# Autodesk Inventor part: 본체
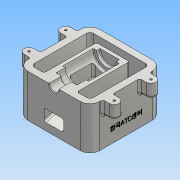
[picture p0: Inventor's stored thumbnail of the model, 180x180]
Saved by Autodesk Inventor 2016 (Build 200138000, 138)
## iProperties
Created: 2018-01
Part Number: 본체
Material: 알루미늄 6061
Document SubType Name: Modeling
Designer: Administrator
Density: 2.7 g/cm^3
Appearance: 알루미늄 - 평지
Mass: 995.217 g
Surface Area: 834.407 cm^2
Volume: 368.599 cm^3
Author: Administrator
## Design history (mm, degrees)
sketch "스케치1"
  geometry: L1 (-55, -55)-(55, -55); L2 (55, -55)-(55, -35.5); L3 (55, 55)-(-55, 55); L4 (-55, 55)-(-55, 35.5); L5 (-55, -55)-(55, 55); L6 (55, -55)-(-55, 55); L7 (-65, -20.5)-(-55, -20.5); L8 (-55, -20.5)-(-55, -35.5); L9 (-55, -35.5)-(-65, -35.5); L10 (-65, -35.5)-(-65, -20.5); L11 (-65, 20.5)-(-55, 20.5); L12 (-55, 20.5)-(-55, 35.5); L13 (-55, 35.5)-(-65, 35.5); L14 (-65, 35.5)-(-65, 20.5); L15 (0, 55)-(0, -55); L16 (55, 35.5)-(65, 35.5); L17 (65, 20.5)-(55, 20.5); L18 (65, -20.5)-(55, -20.5); L19 (55, -35.5)-(65, -35.5); L20 (65, -35.5)-(65, -20.5); L21 (65, 35.5)-(65, 20.5); L22 (-55, 35.5)-(-55, 20.5); L23 (-55, 20.5)-(-55, -20.5); L24 (-55, -20.5)-(-55, -35.5); L25 (-55, -35.5)-(-55, -55); L26 (55, -35.5)-(55, -20.5); L27 (55, -20.5)-(55, 20.5); L28 (55, 20.5)-(55, 35.5); L29 (55, 35.5)-(55, 55); A1 r 7.5 centre (-65, -28) between (-65, -20.5) and (-65, -35.5); A2 r 7.5 centre (-65, 28) between (-65, 35.5) and (-65, 20.5); A3 r 7.5 centre (65, -28) between (65, -35.5) and (65, -20.5); A4 r 7.5 centre (65, 28) between (65, 20.5) and (65, 35.5); 3 further points
  constraints: 58 end point, 30 parallel, 10 symmetric about line, 9 midpoint, 8 point on circle, 7 perpendicular, 4 centre point, 4 point on line, 3 horizontal, 2 other
  dimensions: "d0" = 110 distance of L3.end L3.start; "d1" = 110 distance of L3.start L1.end; "d2" = 27 distance of L3.end point (-55, 28); "d3" = 56 distance of point (-55, -28) point (-55, 28); "d4" = 10 distance of L4.end L13.end; "d5" = 7.5 radius of A2; "d6" = 7.5 radius of A1
extrude "돌출1" new body sketch "스케치1" distance "d7" = 65; taper "d8" = 0 deg
sketch "스케치2"
  geometry: L1 (-55, 55)-(-55, -55) reference; L2 (-65, 35.5)-(-55, 35.5); L3 (-55, 35.5)-(-55, 20.5); L4 (-55, 20.5)-(-65, 20.5); L5 (-65, 20.5)-(-65, 35.5); L6 (-65, -20.5)-(-55, -20.5); L7 (-55, -20.5)-(-55, -35.5); L8 (-55, -35.5)-(-65, -35.5); L9 (-65, -35.5)-(-65, -20.5); L10 (0, 0)-(0, 16.819); L11 (55, -35.5)-(65, -35.5); L12 (65, -35.5)-(65, -20.5); L13 (65, -20.5)-(55, -20.5); L14 (55, 20.5)-(65, 20.5); L15 (65, 20.5)-(65, 35.5); L16 (65, 35.5)-(55, 35.5); A1 r 7.5 centre (-65, 28) between (-65, 35.5) and (-65, 20.5); A2 r 7.5 centre (-65, -28) between (-65, -20.5) and (-65, -35.5); A3 r 7.5 centre (65, -28) between (65, -35.5) and (65, -20.5); A4 r 7.5 centre (65, 28) between (65, 20.5) and (65, 35.5); 1 further point
  constraints: 30 end point, 10 symmetric about line, 8 point on circle, 4 centre point, 4 parallel, 4 point on line, 3 midpoint, 2 horizontal, 2 perpendicular, 1 vertical, 2 other
  dimensions: "d9" = 10 distance of L2.start L2.end; "d10" = 7.5 radius of A1; "d11" = 7.5 radius of A2; "d12" = 27 vertical distance of A1.centre L1.start; "d13" = 56 distance of A2.centre A1.centre
extrude "돌출2" join sketch "스케치2" distance "d14" = 20; taper "d15" = 0 deg
feature "쉘1" dims "d16" = 10
sketch "스케치3"
  geometry: L1 (-45, 0)-(-45, 65) reference; L2 (-45, 8.564)-(35, 30); L3 (45, 0)-(-45, 0) reference; L4 (35, 30)-(35, 65); L5 (20.5, 65)-(-20.5, 65) reference; L6 (-55, 0)-(-55, 65) reference; L7 (-45, 8.564)-(-55, 10.787); L8 (35, 65)-(-45, 65); L9 (-35.5, 65)-(-55, 65) reference; L10 (45, 0)-(45, 65) reference; L11 (55, 0)-(55, 65) reference; 1 further point
  constraints: 8 end point, 3 point on line, 1 collinear, 1 vertical
  dimensions: "d17" = 30 distance from line of L3 L2.end; "d18" = 105 deg angle of L1 L2; "d38" = 20 distance between parallel lines of L11 L4
extrude "돌출3" join sketch "스케치3" stored distance "d22" = 50; taper "d23" = 0 deg
sketch "스케치7"
  geometry: L1 (-55, 0)-(-55, 65) reference; L2 (-55, 11.061)-(20, 31.157); L3 (35, 65)-(35, 30) reference; L4 (35, 30)-(-45, 8.564) reference; L5 (-55, 29.061)-(-17, 39.243); L6 (-17, 39.243)-(-17, 57.924); L7 (20, 31.157)-(20, 57.924); L8 (-17, 57.924)-(-17, 63.66); L9 (20, 57.924)-(20, 63.66); L10 (-17, 63.66)-(20, 63.66); L11 (20.5, 65)-(-20.5, 65) reference; L12 (-55, 29.061)-(-55, 11.061); 1 further point
  constraints: 16 end point, 4 vertical, 2 point on line, 1 collinear, 1 parallel
  dimensions: "d33" = 15 distance from line of L3 L2.end; "d34" = 5 distance between parallel lines of L4 L2; "d35" = 18 distance of L2.start L5.start; "d36" = 75 deg angle of L5 L1; "d37" = 37 distance between parallel lines of L6 L7
extrude "돌출4" cut sketch "스케치7" stored distance "d39" = 30; taper "d40" = 0 deg
sketch "스케치9"
  geometry: L1 (-25, 35)-(25, 35) reference; L2 (-55, -55)-(55, -55) reference; L3 (0, 35)-(0, -55); L4 (-55, -55)-(55, -55) reference; L5 (-7.5, -55)-(-7.5, -36); L6 (-16, -22)-(-16, -36); L7 (-20, 25)-(-20, -22); L8 (-15, 30)-(-15, 25); L9 (-15, 25)-(-20, 25); L10 (-20, -22)-(-16, -22); L11 (-16, -36)-(-7.5, -36); L12 (-15, 30)-(0, 30); L13 (-7.5, -55)-(0, -55); 1 further point
  constraints: 20 end point, 4 perpendicular, 3 vertical, 2 midpoint, 2 point on line, 1 collinear, 1 horizontal
  dimensions: "d41" = 15 diameter of L5 L3; "d42" = 32 diameter of L6 L3; "d43" = 40 diameter of L7 L3; "d44" = 30 diameter of L8 L3; "d45" = 5 distance of L8.start L8.end; "d46" = 47 distance of L7.start L7.end; "d47" = 14 distance of L6.start L6.end; "d48" = 19 distance of L5.start L5.end
revolve "회전1" sketch "스케치9" stored, may be unused: angle "d49" = 90 deg
hole "구멍1" diameter "d52" = 3.242; stored, may be unused: countersink angle "d56" = 90 deg, drill point angle "d58" = 118 deg; dims "d50" = 10, "d51" = 10, "d53" = 9, "d54" = 4, "d55" = 2, "d57" = 11
hole "구멍2" diameter "d61" = 3.242; stored, may be unused: countersink angle "d65" = 90 deg, drill point angle "d67" = 118 deg; dims "d59" = 10, "d60" = 10, "d62" = 9, "d63" = 4, "d64" = 2, "d66" = 11
hole "구멍3" diameter "d70" = 3.242; stored, may be unused: countersink angle "d74" = 90 deg, drill point angle "d76" = 118 deg; dims "d68" = 10, "d69" = 10, "d71" = 9, "d72" = 4, "d73" = 2, "d75" = 11
hole "구멍4" diameter "d79" = 3.242; stored, may be unused: countersink angle "d83" = 90 deg, drill point angle "d85" = 118 deg; dims "d77" = 10, "d78" = 10, "d80" = 9, "d81" = 4, "d82" = 2, "d84" = 11
fillet "모깎기1" dims "d86" = 15
fillet "모깎기2" dims "d87" = 5
fillet "모깎기4" dims "d89" = 3
fillet "모깎기5" dims "d90" = 3
sketch "스케치11"
  geometry: L1 (0, 0)-(0, 80) reference; L2 (-65, -15)-(0, -15) reference; 2 further points
  constraints: 1 other
  dimensions: "d103" = 55 distance from line of L2 point (-20, 40); "d104" = 20 distance from line of L1 point (-20, 40)
feature "엠보싱2" sketch "스케치11" dims "d0" = 110, "d1" = 110, "d2" = 27, "d3" = 56, "d4" = 10, "d5" = 7.5, "d6" = 7.5, "d105" = 0.5, "d106" = 0
fillet "모깎기11" dims "d107" = 1
chamfer "모따기2" distance "d108" = 1; stored, may be unused: second distance "d109" = 2, angle "d110" = 45 deg
chamfer "모따기3" distance "d111" = 1; stored, may be unused: second distance "d112" = 2, angle "d113" = 45 deg
fillet "모깎기12" dims "d114" = 3
fillet "모깎기13" dims "d115" = 3
fillet "모깎기14" dims "d116" = 3
fillet "모깎기15" dims "d117" = 3
fillet "모깎기16" dims "d118" = 3
fillet "모깎기17" dims "d119" = 3
fillet "모깎기18" dims "d120" = 3
node "솔리드1"
mirror "대칭1"
